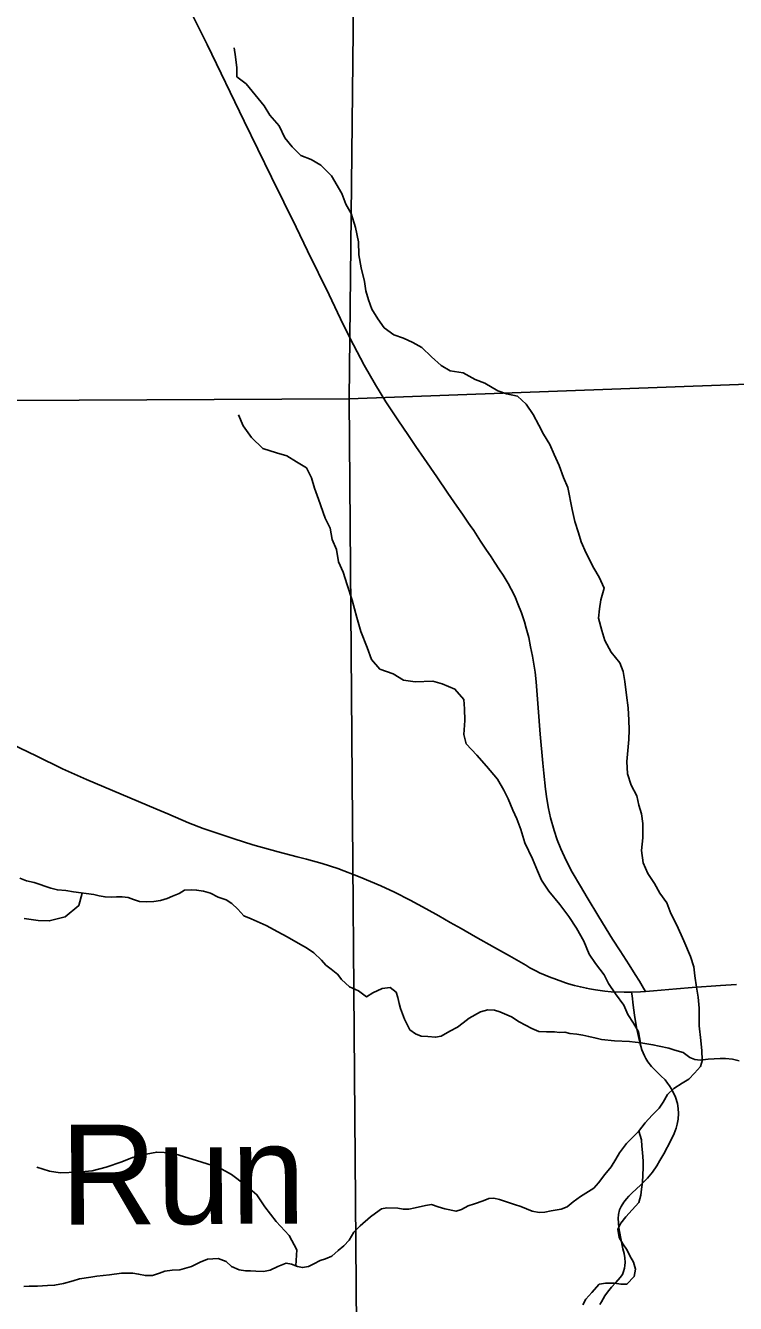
# Model space of a CAD drawing. Extents: x 1985906 to 2360102, y 891258 to 1222054.
# Drawn here: x 2101406 to 2104960, y 1026196 to 1032595 of the extents above; entities that cross this region are included whole.
import ezdxf

# ---------------------------------------------------------------- set-up
doc = ezdxf.new("R2010")
doc.units = 0
for name, color, linetype in [('GM_X_Minor_River', 7, 'Continuous'), ('GM_X_Minor_River_Text', 7, 'Continuous'), ('GM_X_Section', 7, 'Continuous'), ('GM_X_State_Route', 7, 'Continuous'), ('GM_X_Township_Road', 7, 'Continuous')]:
    doc.layers.add(name, color=color, linetype=linetype)

msp = doc.modelspace()

# ---------------------------------------------------------------- linework, layer by layer
at = {"layer": 'GM_X_Minor_River'}
for points in [[(2104793.5, 1027415.5), (2104791.4, 1027460.7), (2104787.1, 1027512.9), (2104778.7, 1027587.1), (2104778.2, 1027675.4), (2104773.9, 1027729.6), (2104765.7, 1027779.8), (2104757.3, 1027835.9), (2104751.1, 1027882.1), (2104734.8, 1027934.2), (2104702.3, 1028012.3), (2104665.9, 1028090.5), (2104637.5, 1028148.5), (2104617.2, 1028202.7), (2104580.9, 1028250.7), (2104554.6, 1028298.7), (2104522.2, 1028348.8), (2104497.9, 1028402.9), (2104489.6, 1028465.1), (2104497.3, 1028527.3), (2104496.9, 1028599.6), (2104490.6, 1028647.8), (2104476.4, 1028691.8), (2104466.1, 1028738), (2104437.8, 1028792), (2104419.4, 1028848.2), (2104417.1, 1028910.4), (2104426.6, 1029020.8), (2104428.3, 1029069), (2104426.1, 1029117.2), (2104423.7, 1029179.4), (2104415.4, 1029241.6), (2104407, 1029309.8), (2104398.8, 1029360), (2104380.5, 1029404.1), (2104338.1, 1029458.1), (2104305.8, 1029516.2), (2104291.5, 1029566.3), (2104275.1, 1029628.4), (2104278.9, 1029674.6), (2104286.7, 1029718.8), (2104302.4, 1029777.1), (2104278.1, 1029833.2), (2104251.8, 1029877.3), (2104213.3, 1029953.4), (2104187, 1030009.5), (2104174.7, 1030055.6), (2104156.4, 1030111.7), (2104142, 1030171.9), (2104121.4, 1030282.2), (2104099.1, 1030332.3), (2104076.8, 1030392.4), (2104052.4, 1030446.5), (2104030.1, 1030496.6), (2103999.8, 1030548.7), (2103975.5, 1030594.7), (2103947.2, 1030646.8), (2103912.9, 1030698.8), (2103868.6, 1030738.8), (2103814.4, 1030750.6), (2103770.2, 1030766.4), (2103705.9, 1030804.3), (2103657.7, 1030822.1), (2103597.4, 1030856), (2103531.2, 1030865.7), (2103487, 1030893.6), (2103438.7, 1030935.6), (2103390.4, 1030983.5), (2103344.1, 1031007.4), (2103297.9, 1031029.3), (2103249.8, 1031047.1), (2103201.5, 1031081), (2103169.2, 1031127.1), (2103138.9, 1031175.1), (2103122.6, 1031221.2), (2103110.3, 1031267.3), (2103102.1, 1031313.5), (2103085.7, 1031381.7), (2103075.3, 1031447.8), (2103073, 1031512.1), (2103058.6, 1031584.3), (2103036.2, 1031654.4), (2103009.9, 1031700.5), (2102989.6, 1031754.6), (2102937, 1031842.7), (2102884.6, 1031896.7), (2102836.4, 1031924.6), (2102784.2, 1031944.4), (2102739.9, 1031988.4), (2102703.6, 1032032.4), (2102675.2, 1032092.5), (2102628.8, 1032146.5), (2102600.5, 1032192.5), (2102509.8, 1032302.5), (2102463.5, 1032338.4), (2102463.3, 1032382.6), (2102457, 1032438.8), (2102450.7, 1032482.9)], [(2104485.2, 1027501.6), (2104482.5, 1027509.5), (2104474.3, 1027555.6), (2104450, 1027599.7), (2104421.7, 1027643.7), (2104401.4, 1027689.8), (2104359.1, 1027745.8), (2104324.7, 1027797.8), (2104302.5, 1027841.9), (2104260.1, 1027897.9), (2104227.8, 1027945.9), (2104201.4, 1028010), (2104165, 1028076.1), (2104126.6, 1028134.2), (2104080.2, 1028194.2), (2104025.7, 1028260.2), (2103989.4, 1028316.2), (2103969.1, 1028362.3), (2103944.7, 1028422.4), (2103906.3, 1028502.5), (2103885.9, 1028568.7), (2103865.6, 1028622.8), (2103845.3, 1028666.9), (2103823, 1028723), (2103800.7, 1028767.1), (2103768.3, 1028821.1), (2103713.9, 1028887.1), (2103665.5, 1028941.1), (2103611.1, 1028999.1), (2103600.9, 1029045.2), (2103604.5, 1029115.5), (2103604.2, 1029173.7), (2103599.9, 1029219.8), (2103555.6, 1029271.8), (2103491.3, 1029299.6), (2103445.2, 1029311.5), (2103357, 1029309.1), (2103298.9, 1029316.8), (2103246.6, 1029348.7), (2103180.3, 1029372.5), (2103138, 1029420.5), (2103115.7, 1029480.6), (2103085.2, 1029560.8), (2103064.8, 1029630.9), (2103040.3, 1029717.2), (2103015.8, 1029795.3), (2102995.5, 1029857.5), (2102973.1, 1029909.6), (2102962.8, 1029971.8), (2102940.5, 1030021.8), (2102930.2, 1030078), (2102905.9, 1030128.1), (2102873.3, 1030224.3), (2102853, 1030278.4), (2102836.7, 1030330.5), (2102812.4, 1030380.6), (2102762.1, 1030410.5), (2102713.9, 1030440.4), (2102661.7, 1030456.2), (2102593.5, 1030478), (2102537.1, 1030531.9), (2102494.7, 1030590), (2102472.3, 1030646.1)], [(2103330, 1027566.4), (2103315.8, 1027592.5), (2103303.7, 1027620.5), (2103283.4, 1027672.6), (2103277.2, 1027698.7), (2103269, 1027728.8), (2103260.9, 1027754.8), (2103230.7, 1027778.8), (2103190.7, 1027772.6), (2103144.7, 1027752.3), (2103112.7, 1027732.1), (2103072.5, 1027762), (2103028.3, 1027781.9), (2102988, 1027817.8), (2102969.9, 1027843.8), (2102935.7, 1027869.8), (2102909.5, 1027889.7), (2102887.3, 1027915.7), (2102849.1, 1027951.7), (2102812.9, 1027977.6), (2102782.7, 1027993.5), (2102716.4, 1028031.4), (2102668.2, 1028057.3), (2102609.9, 1028089.1), (2102535.6, 1028122.9), (2102499.4, 1028136.8), (2102469.2, 1028170.8), (2102439, 1028198.7), (2102410.9, 1028216.7), (2102370.7, 1028230.5), (2102332.5, 1028250.4), (2102296.4, 1028260.3), (2102262.3, 1028266.2), (2102234.3, 1028268.1), (2102202.2, 1028265.9), (2102174.2, 1028249.7), (2102142.2, 1028235.5), (2102114.2, 1028223.4), (2102082.2, 1028213.2), (2102048.2, 1028209), (2102010.1, 1028206.8), (2101976.1, 1028208.7), (2101946, 1028218.6), (2101919.8, 1028228.5), (2101889.8, 1028232.4), (2101861.7, 1028232.2), (2101833.7, 1028230.1), (2101803.6, 1028232), (2101773.5, 1028237.9), (2101747.4, 1028243.8), (2101645.2, 1028257.3), (2101607.1, 1028263.2), (2101565, 1028267), (2101532.9, 1028274.9), (2101448.5, 1028304.6), (2101410.4, 1028312.5), (2101376.3, 1028326.4)], [(2101689.7, 1028251.4), (2101672.2, 1028189.1), (2101604.6, 1028132.6), (2101524.7, 1028112.1), (2101468.7, 1028113.8), (2101398.6, 1028123.4)], [(2104978, 1027411.3), (2104945.9, 1027419.2), (2104909.8, 1027423.1), (2104883.7, 1027423), (2104823.6, 1027418.7), (2104783.6, 1027414.5), (2104757.5, 1027418.4), (2104731.4, 1027428.3), (2104699.2, 1027452.2), (2104657.1, 1027464.1), (2104627, 1027474), (2104578.8, 1027483.8), (2104546.7, 1027491.7), (2104486.6, 1027501.5), (2104430.4, 1027507.2), (2104354.3, 1027510.9), (2104290.1, 1027518.6), (2104262, 1027524.5), (2104225.9, 1027532.4), (2104195.8, 1027540.3), (2104165.7, 1027544.2), (2104131.6, 1027548), (2104105.6, 1027553.9), (2104079.5, 1027553.8), (2104053.5, 1027555.7), (2104013.4, 1027555.5), (2103975.3, 1027557.3), (2103941.1, 1027573.2), (2103876.8, 1027607.1), (2103838.7, 1027631), (2103780.4, 1027656.8), (2103754.3, 1027664.7), (2103720.2, 1027666.6), (2103684.2, 1027656.4), (2103626.3, 1027624), (2103596.3, 1027601.8), (2103568.4, 1027579.6), (2103530.4, 1027559.3), (2103486.5, 1027535), (2103458.4, 1027528.9), (2103420.3, 1027532.7), (2103386.3, 1027534.6), (2103358.2, 1027546.5), (2103330, 1027566.4)], [(2104795.3, 1027415.7), (2104785.8, 1027382.4), (2104755.9, 1027350.1), (2104726, 1027319.9), (2104694, 1027299.6), (2104652.1, 1027273.3), (2104620.2, 1027243.1), (2104598.3, 1027204.8), (2104578.4, 1027174.7), (2104542.6, 1027138.4), (2104508.7, 1027100.1), (2104474.8, 1027057.8), (2104415, 1026997.2), (2104379.2, 1026950.9), (2104361.3, 1026918.7), (2104337.5, 1026880.5), (2104305.6, 1026842.2), (2104273.8, 1026799.9), (2104251.9, 1026773.7), (2104223.9, 1026757.5), (2104184, 1026731.2), (2104148, 1026704.9), (2104118.1, 1026680.7), (2104088.1, 1026668.5), (2104038.1, 1026660.3), (2104006, 1026654.1), (2103978, 1026652), (2103941.9, 1026657.8), (2103913.8, 1026669.8), (2103885.7, 1026681.7), (2103853.5, 1026691.6), (2103813.4, 1026705.4), (2103779.3, 1026717.3), (2103751.2, 1026723.2), (2103725.1, 1026721.1), (2103697.1, 1026710.9), (2103653.1, 1026694.7), (2103621.1, 1026684.5), (2103589.2, 1026666.3), (2103561.2, 1026658.1), (2103505, 1026669.9), (2103470.9, 1026679.8), (2103438.7, 1026691.7), (2103408.7, 1026687.5), (2103356.7, 1026675.2), (2103324.6, 1026669.1), (2103296.6, 1026668.9), (2103270.5, 1026672.8), (2103214.4, 1026674.6), (2103188.4, 1026670.5), (2103158.4, 1026648.2), (2103132.5, 1026630.1), (2103080.6, 1026585.7), (2103048.7, 1026553.4), (2103026.9, 1026513.2), (2102999, 1026484.9), (2102971, 1026460.7), (2102939.1, 1026432.4), (2102907.1, 1026420.2), (2102881.1, 1026412.1), (2102849.2, 1026393.9), (2102823.2, 1026381.7), (2102793.1, 1026375.6), (2102767.1, 1026381.5), (2102736.9, 1026393.4), (2102710.9, 1026397.3), (2102668.9, 1026381), (2102630.9, 1026362.8), (2102596.9, 1026356.6), (2102558.8, 1026358.4), (2102532.7, 1026360.3), (2102506.7, 1026360.2), (2102474.6, 1026364.1), (2102436.4, 1026382), (2102410.2, 1026405.9), (2102370.1, 1026421.8), (2102316, 1026417.6), (2102280, 1026403.3), (2102236, 1026381.1), (2102178, 1026364.7), (2102139.9, 1026362.6), (2102103.9, 1026358.4), (2102075.9, 1026348.2), (2102041.9, 1026336), (2102005.8, 1026335.8), (2101971.7, 1026343.7), (2101943.7, 1026347.6), (2101885.5, 1026347.3), (2101825.5, 1026339), (2101763.4, 1026332.7), (2101733.3, 1026328.6), (2101675.3, 1026320.3), (2101643.3, 1026310.1), (2101595.2, 1026295.8), (2101551.2, 1026287.6), (2101515.1, 1026285.4), (2101465.1, 1026283.2), (2101423, 1026283), (2101396.9, 1026280.9)], [(2104475.7, 1027058.8), (2104489.1, 1027015.7), (2104491.3, 1026983.5), (2104495.4, 1026951.4), (2104497.7, 1026909.3), (2104497.8, 1026877.2), (2104496, 1026839), (2104494.2, 1026802.9), (2104490.4, 1026768.8), (2104486.5, 1026738.6), (2104476.7, 1026702.4), (2104442.8, 1026664.2), (2104410.9, 1026629.9), (2104387.1, 1026597.7), (2104371.2, 1026567.5), (2104377.4, 1026527.3), (2104395.6, 1026495.3), (2104417.8, 1026463.3), (2104432, 1026435.2), (2104450.2, 1026403.2), (2104460.4, 1026367.1), (2104452.6, 1026331), (2104416.7, 1026292.7), (2104386.6, 1026292.5), (2104354.5, 1026298.4), (2104310.5, 1026298.2), (2104278.4, 1026292), (2104240.6, 1026251.7), (2104210.7, 1026217.4), (2104196.8, 1026189.3)], [(2102759.6, 1026384.4), (2102763.5, 1026465.2), (2102725.2, 1026537.1), (2102660.8, 1026606.8), (2102604.4, 1026680.6), (2102564.1, 1026740.4), (2102505.8, 1026790.2), (2102437.5, 1026841.8), (2102373.3, 1026877.5), (2102289.2, 1026903), (2102197, 1026932.5), (2102137, 1026950.2), (2102062.9, 1026953.8), (2102009, 1026943.4), (2101941.1, 1026927), (2101887.2, 1026904.7), (2101809.4, 1026878.2), (2101739.5, 1026859.8), (2101667.5, 1026853.3), (2101579.6, 1026850.8), (2101525.5, 1026858.5), (2101461.4, 1026878.2)]]:
    msp.add_lwpolyline(points, dxfattribs=at)
at = {"layer": 'GM_X_Section'}
for points in [[(2108614.1, 1036304.1), (2108612.2, 1036278.1), (2108603.7, 1030930.8), (2103026, 1030725.8), (2103084, 1036099.3)], [(2097550.9, 1036060.4), (2103084, 1036099.3), (2103026, 1030725.8), (2097619, 1030699.6)], [(2108603.7, 1030930.8), (2108603.9, 1030894.8), (2108547.5, 1025523.2), (2103217.8, 1025431.7), (2103067.7, 1025441), (2103026, 1030725.8)], [(2103026, 1030725.8), (2103067.7, 1025441), (2098032.8, 1025418.6), (2097644.6, 1025416.7), (2097619, 1030699.6)]]:
    msp.add_lwpolyline(points, close=True, dxfattribs=at)
at = {"layer": 'GM_X_State_Route'}
for points in [[(2104510.6, 1027758.5), (2104500.5, 1027774.8), (2104479, 1027809.7), (2104458.3, 1027843.1), (2104428.5, 1027891.2), (2104382.7, 1027961.7), (2104344.5, 1028020.3), (2104276.6, 1028131.5), (2104217.5, 1028229.6), (2104183.8, 1028285.5), (2104142.7, 1028356), (2104112.6, 1028413.8), (2104085.7, 1028472.9), (2104067.7, 1028518.3), (2104051.8, 1028564.5), (2104033.8, 1028627.1), (2104023.4, 1028674.7), (2104015.1, 1028722.7), (2104008.5, 1028771.1), (2104000.1, 1028852.2), (2103995.5, 1028901), (2103981.8, 1029047.5), (2103972.3, 1029177.9), (2103962.3, 1029308.2), (2103956.6, 1029356.6), (2103943.6, 1029436.6), (2103934.6, 1029484), (2103924.9, 1029531.3), (2103913, 1029578.1), (2103904, 1029608.9), (2103888.2, 1029654.8), (2103870.7, 1029700.2), (2103858.1, 1029730.1), (2103851.7, 1029744.7), (2103837.8, 1029773.5), (2103822.3, 1029801.9), (2103796.7, 1029843.2), (2103779.6, 1029869.5), (2103754.1, 1029908.4), (2103736.6, 1029934.4), (2103710.6, 1029973.9), (2103684.5, 1030013.5), (2103649.7, 1030066), (2103632.6, 1030091.1), (2103623.7, 1030103.8), (2103592.9, 1030148.8), (2103565.9, 1030188.1), (2103520.8, 1030253.8), (2103465.1, 1030335.1), (2103402.1, 1030426.8), (2103360.3, 1030487.8), (2103319.2, 1030547.8), (2103273.3, 1030615.8), (2103210, 1030711.5), (2103158.7, 1030795.3), (2103101.8, 1030894.9), (2103047.5, 1030995.9), (2102996.5, 1031098.6), (2102925.6, 1031246.5), (2102817.5, 1031467.5), (2102759.9, 1031585.4), (2102636.5, 1031835.5), (2102499.9, 1032115.7), (2102314.5, 1032499.9), (2102242.1, 1032647.2)], [(2104965.9, 1027793), (2104885.4, 1027787.5), (2104743.1, 1027777.7), (2104664.5, 1027770.9), (2104550.7, 1027761.3), (2104510.6, 1027758.5), (2104485.2, 1027756.8), (2104440.2, 1027755.2), (2104436, 1027755), (2104419.6, 1027754.9), (2104403, 1027754.9), (2104338, 1027757.4), (2104306, 1027759.6), (2104259.7, 1027766.1), (2104229.6, 1027771.9), (2104214.3, 1027774.9), (2104184.3, 1027781), (2104154.5, 1027787.9), (2104124.7, 1027796.5), (2104109.7, 1027801), (2104050.5, 1027822.6), (2104036, 1027828.4), (2104007.4, 1027840.3), (2103979.1, 1027852.3), (2103964.2, 1027859.7), (2103947.9, 1027867.8), (2103931.5, 1027876.8), (2103910.1, 1027889.9), (2103829.2, 1027937), (2103753.7, 1027978.7), (2103659, 1028031.7), (2103587, 1028073.4), (2103531.4, 1028103.8), (2103475, 1028136.8), (2103411.6, 1028171.5), (2103330.8, 1028215.8), (2103252.7, 1028255.8), (2103184.1, 1028287.9), (2103081.7, 1028331.3), (2102969.4, 1028374.2), (2102891.6, 1028399), (2102813, 1028421.1), (2102765.2, 1028432.3), (2102670.3, 1028457.4), (2102544.3, 1028493.5), (2102450.1, 1028522.8), (2102294.9, 1028575.3), (2102221.9, 1028602.7), (2102117.4, 1028647.3), (2102058.8, 1028673.6), (2101711.5, 1028820.6), (2101591.4, 1028873.8), (2101458.4, 1028937.6), (2101177.9, 1029072.4)]]:
    msp.add_lwpolyline(points, dxfattribs=at)
at = {"layer": 'GM_X_Township_Road'}
msp.add_lwpolyline([(2104281.3, 1026190.4), (2104288.8, 1026205.1), (2104306.3, 1026234.4), (2104319.6, 1026252.4), (2104339.9, 1026277.4), (2104361.8, 1026301.6), (2104383.7, 1026325.9), (2104393.9, 1026341.5), (2104400.1, 1026356.3), (2104404.8, 1026372.8), (2104407.1, 1026386.8), (2104407.9, 1026401.7), (2104405.6, 1026425.1), (2104402.5, 1026447), (2104397, 1026470.5), (2104384.5, 1026529.9), (2104376.7, 1026574.4), (2104374.4, 1026600.2), (2104373.6, 1026621.3), (2104375.2, 1026641.6), (2104379.1, 1026664.3), (2104387.7, 1026682.3), (2104400.9, 1026703.4), (2104415, 1026719.8), (2104426, 1026733.1), (2104441.6, 1026748.7), (2104486.2, 1026789.4), (2104520.6, 1026823.8), (2104544.8, 1026854.2), (2104566.7, 1026885.5), (2104582.3, 1026911.3), (2104601.9, 1026945.7), (2104636.3, 1027012.9), (2104652.7, 1027046.5), (2104663.7, 1027074.7), (2104668.4, 1027094.2), (2104673.1, 1027118.4), (2104675.4, 1027148.1), (2104673.8, 1027172.4), (2104670.2, 1027197.7), (2104659.5, 1027228.5), (2104646.5, 1027258.1), (2104638.9, 1027272.3), (2104630.3, 1027285.9), (2104620.8, 1027298.7), (2104608.2, 1027315.4), (2104586.3, 1027336.5), (2104562.9, 1027359.2), (2104539.4, 1027383.4), (2104521.4, 1027406.1), (2104512.1, 1027422.5), (2104504.3, 1027436.6), (2104491.8, 1027466.3), (2104481.6, 1027502.2), (2104465.6, 1027578.8), (2104455.1, 1027640.6), (2104448.1, 1027690.6), (2104442.6, 1027736), (2104440.2, 1027755.2)], dxfattribs=at)

# ---------------------------------------------------------------- texts
at = {"layer": 'GM_X_Minor_River_Text'}
msp.add_text('Run', height=500.13, rotation=0.26201, dxfattribs=at).set_placement((2101580.9, 1026590.9))

doc.saveas('drawing.dxf')
